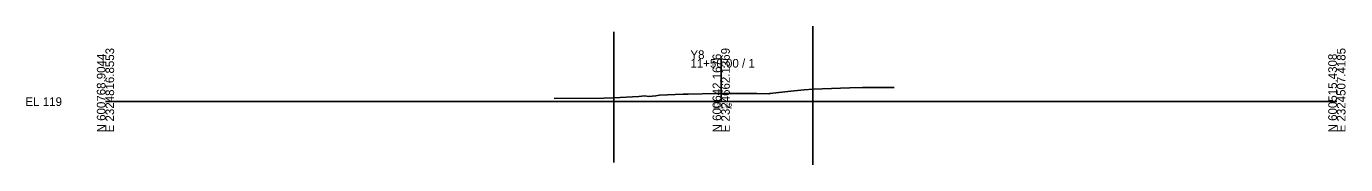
# Model space of a CAD drawing. Extents: x -26 to 2324730, y 979 to 600638.
# Drawn here: x -25.7 to 402.8, y 979.5 to 1024.5 of the extents above; entities that cross this region are included whole.
import ezdxf

# ---------------------------------------------------------------- set-up
doc = ezdxf.new("R2010")
doc.units = 0
for name, color, linetype in [('Default', 7, 'Continuous'), ('Exist CMT Pavement', 7, 'Continuous'), ('Exist Cross Section Cell', 7, 'Continuous'), ('Exist XS Center Line Elevation Label', 7, 'Continuous'), ('Exist XS Ground Line', 7, 'Continuous'), ('Prop XS Earthwork Shape', 7, 'Continuous'), ('Prop XS Exc Vertical Line 1', 7, 'Continuous'), ('Prop XS Exc Vertical Line 4', 7, 'Continuous'), ('Scratch_Level_0', 7, 'Continuous')]:
    doc.layers.add(name, color=color, linetype=linetype)

msp = doc.modelspace()

# ---------------------------------------------------------------- linework, layer by layer
at = {"layer": 'Exist CMT Pavement'}
for p, q in [((200, 1002.62), (200, 1002.72)), ((200, 1002.72), (200.1, 1002.72)), ((200.1, 1002.72), (200.1, 1002.62))]:
    msp.add_line(p, q, dxfattribs=at)
at = {"layer": 'Exist Cross Section Cell'}
for p, q in [((200, 1000), (200, 1013.9)), ((0, 1000), (200, 1000)), ((200, 1000), (400, 1000))]:
    msp.add_line(p, q, dxfattribs=at)
at = {"layer": 'Exist XS Ground Line'}
msp.add_lwpolyline([(145.71, 1001.07), (161.84, 1001.14), (165.15, 1001.26), (173.26, 1001.7), (175.16, 1001.84), (176.38, 1001.67), (178.82, 1001.91), (179.99, 1002.06), (187.69, 1002.39), (188.46, 1002.42), (189.29, 1002.44), (198.31, 1002.62), (200, 1002.62), (207.69, 1002.6), (208.24, 1002.6), (208.9, 1002.6), (211.62, 1002.6), (215.52, 1002.59), (215.83, 1002.63), (222.58, 1003.38), (226.95, 1003.83), (229.87, 1004.08), (238.77, 1004.42), (241.74, 1004.47), (245.88, 1004.57), (254.89, 1004.63), (256.24, 1004.63)], dxfattribs=at)
at = {"layer": 'Prop XS Earthwork Shape'}
msp.add_lwpolyline([(200, 1002.62), (200.1, 1002.62), (200.1, 1002.72), (200, 1002.72)], close=True, dxfattribs=at)
at = {"layer": 'Prop XS Exc Vertical Line 1'}
msp.add_line((165.15, 1022.76), (165.15, 980.16), dxfattribs=at)
at = {"layer": 'Prop XS Exc Vertical Line 4'}
msp.add_line((229.76, 1024.52), (229.76, 979.48), dxfattribs=at)

# ---------------------------------------------------------------- texts
at = {"layer": 'Default'}
msp.add_text('-', height=0.0001, dxfattribs=at).set_placement((0, 1000))
at = {"layer": 'Exist Cross Section Cell'}
for s, p in [('E 2324816.8553', (2.8, 990)), ('E 2324662.1369', (202.8, 990)), ('E 2324507.4185', (402.8, 990)), ('N 600768.9044', (0, 990)), ('N 600642.1676', (200, 990)), ('N 600515.4308', (400, 990))]:
    msp.add_text(s, height=2.8, rotation=90, dxfattribs=at).set_placement(p)
for s, p in [('Y8', (190, 1013.9)), ('11+50.00 / 1', (190, 1011.1)), ('EL 119', (-26, 998.6))]:
    msp.add_text(s, height=2.8, dxfattribs=at).set_placement(p)
at = {"layer": 'Exist XS Center Line Elevation Label'}
msp.add_text('121.62', height=1.5, dxfattribs=at).set_placement((197.33, 997.87))
at = {"layer": 'Scratch_Level_0'}
msp.add_text('RT_Slope_Cut', height=0.02, dxfattribs=at).set_placement((236.42, 1004.33))

doc.saveas('drawing.dxf')
